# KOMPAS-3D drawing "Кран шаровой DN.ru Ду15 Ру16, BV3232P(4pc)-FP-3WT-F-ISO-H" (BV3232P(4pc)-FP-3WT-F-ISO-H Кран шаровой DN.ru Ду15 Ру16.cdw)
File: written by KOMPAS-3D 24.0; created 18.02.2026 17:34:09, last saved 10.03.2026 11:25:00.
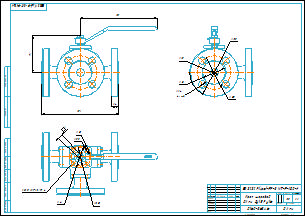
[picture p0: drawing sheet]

Document properties: Автор: R2D2; Форматы листов документа: A2; Полное имя файла: BV3232P(4pc)-FP-3WT-F-ISO-H Кран шаровой DN.ru Ду15 Ру16.m3d; Масса: 3.5; Наименование: Кран шаровой DN.ru Ду15 Ру16; Количество листов документа: 1; Примечание: D160-36346

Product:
- Part/product: Кран шаровой DN.ru Ду15 Ру16  | designation BV3232P(4pc)-FP-3WT-F-ISO-H
    Масса: 3.5
    Раздел спецификации: Прочие изделия
    Примечание: D160-36346

Views: Вид 1, Спереди, Проекционный вид 2
Referenced files in E:\Работа\Зайцев\BV3232P(4pc)-FP-3WL-F-ISO-H Кран шаровой DN.ru Ду15-100 Ру16\DN15\: BV3232P(4pc)-FP-3WL-F-ISO-H Кран шаровой DN.ru Ду15 Ру16.m3d
Referenced files in E:\Работа\Зайцев\BV3232P(4pc)-FP-3WT-F-ISO-H Кран шаровой DN.ru Ду15-100 Ру16\DN15\: BV3232P(4pc)-FP-3WT-F-ISO-H Кран шаровой DN.ru Ду15 Ру16.m3d
Referenced files in E:\Работа\Зайцев\Для компаса\: чертеж DN.ru А3.cdt
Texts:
  BV3232P(4pc)-FP-3WT-F-ISO-H
  чертеж DN.ru А3.cdt
  Кран шаровой
  DN.ru Ду15 Ру16
  Кран шаровой DN.ru Ду15 Ру16
  BV3232P(4pc)-FP-3WT-F-ISO-H Кран шаровой DN.ru Ду15 Ру16
Dimensions and other numbers on the sheet: 0; 3; 2; 4; 150; 14; 72; 95; 65; 45; 15; 4 отв.; 1:1; 1; 3,5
